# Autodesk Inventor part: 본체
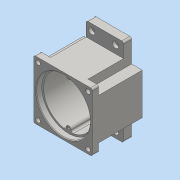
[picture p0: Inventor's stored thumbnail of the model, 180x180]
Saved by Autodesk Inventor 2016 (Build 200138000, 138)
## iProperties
Created: 2020-08
Part Number: 본체
Material: 일반
Document SubType Name: Modeling
Designer: User
Density: 1 g/cm^3
Appearance: 기본값
Author: User
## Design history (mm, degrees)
sketch "스케치1"
  geometry: L1 (-47, 47)-(47, 47); L2 (47, 47)-(47, -47); L3 (47, -47)-(-47, -47); L4 (-47, -47)-(-47, 47); L5 (-47, 47)-(47, -47); L6 (47, 47)-(-47, -47); 1 further point
  constraints: 12 end point, 2 midpoint, 2 parallel, 1 horizontal, 1 perpendicular
  dimensions: "d0" = 94 distance of L2.end L3.end; "d1" = 94 distance of L1.end L2.end
extrude "돌출1" new body sketch "스케치1" distance "d2" = 80; taper "d3" = 0 deg
sketch "스케치2"
  geometry: L1 (30, -70)-(-30, -70); L2 (-30, -70)-(-30, 70); L3 (-30, 70)-(30, 70); L4 (30, 70)-(30, -70); L5 (30, -70)-(-30, 70); L6 (-30, -70)-(30, 70); 1 further point
  constraints: 12 end point, 2 midpoint, 2 parallel, 1 horizontal, 1 perpendicular
  dimensions: "d4" = 60 distance between parallel lines of L4 L2; "d5" = 140 distance between parallel lines of L3 L1
extrude "돌출2" join sketch "스케치2" distance "d6" = 13; taper "d7" = 0 deg
sketch "스케치3"
  geometry: L1 (30, -47)-(47, -47) reference; L2 (47, -47)-(47, 47) reference; L3 (47, 47)-(30, 47) reference; L4 (30, 70)-(30, 47) reference; L5 (-30, 70)-(30, 70) reference; L6 (-30, 47)-(-30, 70) reference; L7 (-30, 47)-(-47, 47) reference; L8 (-47, 47)-(-47, -47) reference; L9 (-47, -47)-(-30, -47) reference; L10 (-30, -70)-(-30, -47) reference; L11 (30, -70)-(-30, -70) reference; L12 (30, -47)-(30, -70) reference; L13 (-47, -47)-(-30, -47); L14 (-30, -47)-(-30, -33); L15 (-30, -33)-(-47, -33); L16 (-47, -33)-(-47, -47); L17 (-30, -70)-(-30, -47) reference; L18 (-47, 47)-(-30, 47); L19 (-30, 47)-(-30, 33); L20 (-30, 33)-(-47, 33); L21 (-47, 33)-(-47, 47); L22 (47, -47)-(30, -47); L23 (30, -47)-(30, -33); L24 (30, -33)-(47, -33); L25 (47, -33)-(47, -47); L26 (47, 47)-(30, 47) reference; L27 (47, 47)-(30, 47); L28 (30, 47)-(30, 33); L29 (30, 33)-(47, 33); L30 (47, 33)-(47, 47); L31 (-30, 47)-(-30, 70) reference; L32 (30, 70)-(30, 47) reference; L33 (30, -47)-(30, -70) reference; 1 further point
  constraints: 32 end point, 8 parallel, 4 collinear, 4 horizontal, 4 perpendicular, 1 point on line
  dimensions: "d8" = 14 distance between parallel lines of L9 L15; "d9" = 14 distance of L18.end L19.end; "d10" = 14 distance of L22.end L23.end; "d11" = 14 distance of L28.end L27.end
extrude "돌출3" cut sketch "스케치3" distance "d12" = 70; taper "d13" = 0 deg
sketch "스케치4"
  geometry: C1 r 27.5 at (-11, 0); 1 further point
  constraints: 1 centre point, 1 horizontal alignment
  dimensions: "d14" = 55 diameter of C1; "d15" = 11 distance of point (0, 0) C1.centre
extrude "돌출4" join sketch "스케치4" distance "d16" = 7; taper "d17" = 0 deg
sketch "스케치5"
  geometry: C1 r 27.5 at (0, 0) reference; 1 further point
hole "구멍1" sketch "스케치5" at (0, 0) diameter "d18" = 25; stored, may be unused: countersink angle "d22" = 90 deg, drill point angle "d24" = 0 deg; dims "d19" = 6, "d20" = 32, "d21" = 8.3, "d23" = 20
sketch "스케치6"
  geometry: L1 (-30, -33)-(-47, -33) reference; L2 (47, 47)-(-47, 47) reference; L3 (-47, 47)-(-47, -47) reference; L4 (-47, -47)-(47, -47) reference; L5 (47, -47)-(47, 47) reference; C1 r 27.5 at (-11, 0) reference; C2 r 43 at (0, 0); 1 further point
  constraints: 1 centre point, 1 coincident
  dimensions: "d25" = 86 diameter of C2
extrude "돌출5" cut sketch "스케치6" distance "d26" = 9; taper "d27" = 0 deg
sketch "스케치7"
  geometry: C1 r 43 at (0, 0) reference; C2 r 40 at (0, 0); 1 further point
  constraints: 1 centre point, 1 coincident
  dimensions: "d28" = 80 diameter of C2
extrude "돌출6" cut sketch "스케치7" distance "d29" = 62; taper "d30" = 0 deg
sketch "스케치8"
  geometry: C1 r 12.5 at (-11, 0) reference; A1 r 21 centre (-11, 0) between (6.119, 12.163) and (6.119, -12.163); A2 r 15 centre (20, 0) between (10.47, -11.584) and (10.47, 11.584); A3 r 3 centre (8.565, 13.901) between (6.119, 12.163) and (10.47, 11.584); A4 r 3 centre (8.565, -13.901) between (10.47, -11.584) and (6.119, -12.163); 1 further point
  constraints: 8 point on circle, 4 centre point, 4 tangent, 1 coincident, 1 horizontal alignment
  dimensions: "d31" = 42 diameter of A1; "d32" = 30 diameter of A2; "d33" = 20 distance of A2.centre point (0, 0); "d34" = 6 diameter of A3; "d35" = 6 diameter of A4
extrude "돌출7" join sketch "스케치8" distance "d36" = 7; taper "d37" = 0 deg
sketch "스케치9"
  geometry: C1 r 9.5 at (20, 0); A1 r 15 centre (20, 0) between (10.47, -11.584) and (10.47, 11.584) reference; 1 further point
  constraints: 1 centre point, 1 coincident
  dimensions: "d38" = 19 diameter of C1
extrude "돌출8" cut sketch "스케치9" distance "d39" = 10; taper "d40" = 0 deg
sketch "스케치10"
  geometry: C1 r 17.5 at (-11, 0); A1 r 21 centre (-11, 0) between (6.119, 12.163) and (6.119, -12.163) reference; 1 further point
  constraints: 1 centre point, 1 coincident
  dimensions: "d41" = 35 diameter of C1
extrude "돌출9" cut sketch "스케치10" distance "d42" = 10; taper "d43" = 0 deg
sketch "스케치11"
  geometry: C1 r 40 at (0, 0) reference; C2 r 43 at (0, 0) reference; A1 r 36 centre (0, 0) between (0, 36) and (-4.045, 35.772); A2 r 4 centre (0, 36) between (-3.995, 36.19) and (3.995, 36.19); A3 r 3 centre (6.992, 36.333) between (7.559, 39.279) and (4.045, 35.772); A4 r 3 centre (-6.992, 36.333) between (-4.045, 35.772) and (-7.559, 39.279); A5 r 40 centre (0, 0) between (-7.559, 39.279) and (7.559, 39.279) reference; 1 further point
  constraints: 13 point on circle, 4 centre point, 4 tangent, 1 coincident, 1 vertical alignment
  dimensions: "d44" = 72 diameter of A1; "d45" = 8 diameter of A2; "d46" = 6 diameter of A3; "d47" = 6 diameter of A4
extrude "돌출10" join sketch "스케치11" distance "d48" = 71; taper "d49" = 0 deg
sketch "스케치12"
  geometry: A1 r 4 centre (0, 36) between (-3.995, 36.19) and (3.995, 36.19) reference; 1 further point
hole "구멍2" sketch "스케치12" at (0, 36) diameter "d50" = 3.242; stored, may be unused: countersink angle "d54" = 90 deg, drill point angle "d56" = 118 deg; dims "d51" = 7, "d52" = 32, "d53" = 8.3, "d55" = 9
sketch "스케치13"
  geometry: L1 (47, -47)-(47, 47) reference; L2 (-47, -47)-(47, -47) reference; C1 r 3.5 at (40, -40); 1 further point
  constraints: 1 centre point
  dimensions: "d57" = 7 diameter of C1; "d58" = 7 distance from line of L1 C1.centre; "d59" = 7 distance from line of L2 C1.centre
extrude "돌출11" cut sketch "스케치13" distance "d60" = 71; taper "d61" = 0 deg
sketch "스케치14"
  geometry: 2 further points
  dimensions: "d68" = 17 horizontal distance of point (0, 0) point (17, 60); "d69" = 60 vertical distance of point (0, 0) point (17, 60)
hole "구멍3" sketch "스케치14" at (17, 60) diameter "d70" = 4.5; stored, may be unused: countersink angle "d74" = 90 deg, drill point angle "d76" = 118 deg; dims "d71" = 7, "d72" = 10, "d73" = 5, "d75" = 9
sketch "스케치15" dims "d0" = 94, "d1" = 94
  geometry: L1 (94, 0)-(0, 0) reference; 3 further points
  constraints: 1 midpoint, 1 vertical alignment, 1 other
  dimensions: "d83" = 40 distance from line of point (47, 40) L1
feature "엠보싱1" sketch "스케치15" dims "d0" = 94, "d1" = 94, "d84" = 0.5, "d85" = 0
chamfer "모따기1" distance "d86" = 0.8; stored, may be unused: second distance "d87" = 2, angle "d88" = 30 deg
fillet "모깎기1" dims "d89" = 3
fillet "모깎기2" dims "d90" = 3
sketch "스케치17"
  geometry: C1 r 17.5 at (-11, 0) reference; C2 r 9.5 at (20, 0) reference; C3 r 11 at (20, 0); A1 r 15 centre (20, 0) between (10.47, -11.584) and (10.47, 11.584) reference; A2 r 3 centre (8.565, 13.901) between (6.119, 12.163) and (10.47, 11.584) reference; A3 r 21 centre (-11, 0) between (6.119, 12.163) and (6.119, -12.163) reference; A4 r 3 centre (8.565, -13.901) between (10.47, -11.584) and (6.119, -12.163) reference; 1 further point
  constraints: 1 centre point, 1 coincident
  dimensions: "d95" = 22 diameter of C3
extrude "돌출12" cut sketch "스케치17" distance "d96" = 7; taper "d97" = 0 deg
chamfer "모따기3" distance "d98" = 1; stored, may be unused: second distance "d99" = 2, angle "d100" = 30 deg
fillet "모깎기4" dims "d101" = 3
node "솔리드1"
pattern_linear "직사각형 패턴1" dims "d64" = 80
pattern_linear "직사각형 패턴2" dims "d79" = 38
mirror "대칭2"
node "투영된 루프1"
node "투영된 루프2"
node "투영된 루프3"
node "투영된 루프4"
node "투영된 루프5"
node "투영된 루프7"
